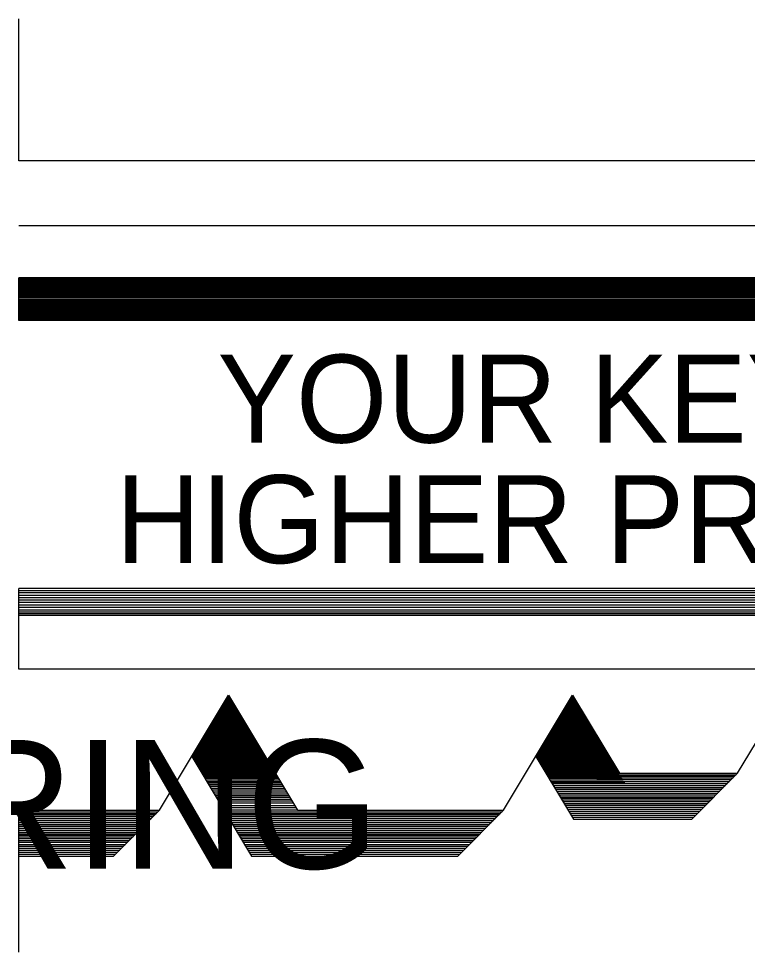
# Model space of a CAD drawing. Extents: x 22378.6 to 22422.6, y 22377.7 to 22411.7.
# Drawn here: x 22382.04 to 22382.601, y 22378.838 to 22379.557 of the extents above; entities that cross this region are included whole.
import ezdxf

# ---------------------------------------------------------------- set-up
doc = ezdxf.new("R2010")
doc.units = 0
for name, color, linetype in [('Level 1', 7, 'Continuous'), ('Level 10', 7, 'Continuous'), ('Level 2', 7, 'Continuous'), ('Level 7', 7, 'Continuous')]:
    doc.layers.add(name, color=color, linetype=linetype)

msp = doc.modelspace()

# ---------------------------------------------------------------- linework, layer by layer
at = {"layer": 'Level 1'}
msp.add_line((22382.04032, 22379.32481), (22382.04032, 22379.35744), dxfattribs=at)
at = {"layer": 'Level 10'}
msp.add_line((22383.12182, 22379.39769), (22382.04032, 22379.39769), dxfattribs=at)
at = {"layer": 'Level 2'}
for p, q in [((22383.17045, 22379.35744), (22382.04032, 22379.35744)), ((22383.17145, 22379.35669), (22382.04032, 22379.35669)), ((22383.17232, 22379.35594), (22382.04032, 22379.35594)), ((22383.17332, 22379.35506), (22382.04032, 22379.35506)), ((22383.17445, 22379.35419), (22382.04032, 22379.35419)), ((22383.17545, 22379.35331), (22382.04032, 22379.35331)), ((22383.1767, 22379.35231), (22382.04032, 22379.35231)), ((22383.1777, 22379.35144), (22382.04032, 22379.35144)), ((22383.17895, 22379.35044), (22382.04032, 22379.35044)), ((22383.1802, 22379.34944), (22382.04032, 22379.34944)), ((22383.1812, 22379.34856), (22382.04032, 22379.34856)), ((22383.18232, 22379.34756), (22382.04032, 22379.34756)), ((22383.1837, 22379.34656), (22382.04032, 22379.34656)), ((22383.1847, 22379.34569), (22382.04032, 22379.34569)), ((22383.1857, 22379.34481), (22382.04032, 22379.34481)), ((22383.18695, 22379.34381), (22382.04032, 22379.34381)), ((22383.1882, 22379.34281), (22382.04032, 22379.34281)), ((22383.18932, 22379.34181), (22382.04032, 22379.34181)), ((22383.1907, 22379.34069), (22382.04032, 22379.34069)), ((22383.19182, 22379.33981), (22382.04032, 22379.33981)), ((22383.19295, 22379.33881), (22382.04032, 22379.33881)), ((22383.19432, 22379.33769), (22382.04032, 22379.33769)), ((22383.19557, 22379.33669), (22382.04032, 22379.33669)), ((22383.19645, 22379.33594), (22382.04032, 22379.33594)), ((22383.1977, 22379.33494), (22382.04032, 22379.33494)), ((22383.19882, 22379.33394), (22382.04032, 22379.33394)), ((22383.19995, 22379.33306), (22382.04032, 22379.33306)), ((22383.20095, 22379.33219), (22382.04032, 22379.33219)), ((22383.20195, 22379.33144), (22382.04032, 22379.33144)), ((22383.20332, 22379.33031), (22382.04032, 22379.33031)), ((22383.2042, 22379.32956), (22382.04032, 22379.32956)), ((22383.2052, 22379.32869), (22382.04032, 22379.32869)), ((22383.20607, 22379.32794), (22382.04032, 22379.32794)), ((22383.20707, 22379.32719), (22382.04032, 22379.32719)), ((22383.20782, 22379.32656), (22382.04032, 22379.32656)), ((22383.2087, 22379.32581), (22382.04032, 22379.32581)), ((22383.20932, 22379.32531), (22382.04032, 22379.32531)), ((22383.20995, 22379.32481), (22382.04032, 22379.32481)), ((22383.26782, 22379.11831), (22382.04032, 22379.11831)), ((22382.04032, 22379.05631), (22382.04032, 22379.11831)), ((22383.26582, 22379.11669), (22382.04032, 22379.11669)), ((22383.2637, 22379.11494), (22382.04032, 22379.11494)), ((22383.26132, 22379.11294), (22382.04032, 22379.11294)), ((22383.25932, 22379.11131), (22382.04032, 22379.11131)), ((22383.25695, 22379.10931), (22382.04032, 22379.10931)), ((22383.25482, 22379.10756), (22382.04032, 22379.10756)), ((22383.25257, 22379.10569), (22382.04032, 22379.10569)), ((22383.25007, 22379.10369), (22382.04032, 22379.10369)), ((22383.24782, 22379.10181), (22382.04032, 22379.10181)), ((22383.2457, 22379.10006), (22382.04032, 22379.10006)), ((22383.2442, 22379.09881), (22382.04032, 22379.09881)), ((22383.24282, 22379.09769), (22382.04032, 22379.09769)), ((22383.19282, 22379.05631), (22382.04032, 22379.05631)), ((22382.19745, 22379.02906), (22382.2062, 22379.02906)), ((22382.19807, 22379.03006), (22382.20557, 22379.03006)), ((22382.1987, 22379.03106), (22382.20495, 22379.03106)), ((22382.19932, 22379.03206), (22382.20432, 22379.03206)), ((22382.19982, 22379.03306), (22382.20382, 22379.03306)), ((22382.20045, 22379.03406), (22382.2032, 22379.03406)), ((22382.20107, 22379.03506), (22382.20257, 22379.03506)), ((22382.4622, 22379.02906), (22382.47095, 22379.02906)), ((22382.46282, 22379.03006), (22382.47032, 22379.03006)), ((22382.46345, 22379.03106), (22382.4697, 22379.03106)), ((22382.46407, 22379.03206), (22382.46907, 22379.03206)), ((22382.46457, 22379.03306), (22382.46857, 22379.03306)), ((22382.46507, 22379.03381), (22382.46807, 22379.03381)), ((22382.46557, 22379.03456), (22382.46757, 22379.03456)), ((22382.46595, 22379.03531), (22382.4672, 22379.03531)), ((22382.19345, 22379.02206), (22382.21032, 22379.02206)), ((22382.19382, 22379.02306), (22382.2097, 22379.02306)), ((22382.19445, 22379.02406), (22382.2092, 22379.02406)), ((22382.19507, 22379.02506), (22382.20857, 22379.02506)), ((22382.1957, 22379.02606), (22382.20795, 22379.02606)), ((22382.19632, 22379.02706), (22382.20732, 22379.02706)), ((22382.19682, 22379.02806), (22382.2067, 22379.02806)), ((22382.4582, 22379.02206), (22382.47507, 22379.02206)), ((22382.45857, 22379.02306), (22382.47445, 22379.02306)), ((22382.4592, 22379.02406), (22382.47395, 22379.02406)), ((22382.45982, 22379.02506), (22382.47332, 22379.02506)), ((22382.46045, 22379.02606), (22382.4727, 22379.02606)), ((22382.46107, 22379.02706), (22382.47207, 22379.02706)), ((22382.46157, 22379.02806), (22382.47145, 22379.02806)), ((22382.18907, 22379.01506), (22382.21457, 22379.01506)), ((22382.1897, 22379.01606), (22382.21395, 22379.01606)), ((22382.19032, 22379.01706), (22382.21332, 22379.01706)), ((22382.19095, 22379.01806), (22382.2127, 22379.01806)), ((22382.19157, 22379.01906), (22382.2122, 22379.01906)), ((22382.1922, 22379.02006), (22382.21157, 22379.02006)), ((22382.19282, 22379.02106), (22382.21095, 22379.02106)), ((22382.45382, 22379.01506), (22382.47932, 22379.01506)), ((22382.45445, 22379.01606), (22382.4787, 22379.01606)), ((22382.45507, 22379.01706), (22382.47807, 22379.01706)), ((22382.4557, 22379.01806), (22382.47745, 22379.01806)), ((22382.45632, 22379.01906), (22382.47695, 22379.01906)), ((22382.45695, 22379.02006), (22382.47632, 22379.02006)), ((22382.45757, 22379.02106), (22382.4757, 22379.02106)), ((22382.18495, 22379.00806), (22382.2187, 22379.00806)), ((22382.18545, 22379.00906), (22382.21807, 22379.00906)), ((22382.18607, 22379.01006), (22382.21757, 22379.01006)), ((22382.1867, 22379.01106), (22382.21695, 22379.01106)), ((22382.18732, 22379.01206), (22382.21632, 22379.01206)), ((22382.18795, 22379.01306), (22382.2157, 22379.01306)), ((22382.18845, 22379.01406), (22382.21507, 22379.01406)), ((22382.4497, 22379.00806), (22382.48345, 22379.00806)), ((22382.4502, 22379.00906), (22382.48282, 22379.00906)), ((22382.45082, 22379.01006), (22382.48232, 22379.01006)), ((22382.45145, 22379.01106), (22382.4817, 22379.01106)), ((22382.45207, 22379.01206), (22382.48107, 22379.01206)), ((22382.4527, 22379.01306), (22382.48045, 22379.01306)), ((22382.4532, 22379.01406), (22382.47982, 22379.01406)), ((22382.1802, 22379.00006), (22382.22345, 22379.00006)), ((22382.18082, 22379.00106), (22382.22295, 22379.00106)), ((22382.18145, 22379.00206), (22382.22232, 22379.00206)), ((22382.18207, 22379.00306), (22382.2217, 22379.00306)), ((22382.1827, 22379.00406), (22382.22107, 22379.00406)), ((22382.18332, 22379.00506), (22382.22057, 22379.00506)), ((22382.1837, 22379.00606), (22382.21995, 22379.00606)), ((22382.18432, 22379.00706), (22382.21932, 22379.00706)), ((22382.44495, 22379.00006), (22382.4882, 22379.00006)), ((22382.44557, 22379.00106), (22382.4877, 22379.00106)), ((22382.4462, 22379.00206), (22382.48707, 22379.00206)), ((22382.44682, 22379.00306), (22382.48645, 22379.00306)), ((22382.44745, 22379.00406), (22382.48582, 22379.00406)), ((22382.44807, 22379.00506), (22382.48532, 22379.00506)), ((22382.44845, 22379.00606), (22382.4847, 22379.00606)), ((22382.44907, 22379.00706), (22382.48407, 22379.00706)), ((22382.17595, 22378.99306), (22382.2277, 22378.99306)), ((22382.17645, 22378.99406), (22382.22707, 22378.99406)), ((22382.17707, 22378.99506), (22382.22645, 22378.99506)), ((22382.1777, 22378.99606), (22382.22595, 22378.99606)), ((22382.17832, 22378.99706), (22382.22532, 22378.99706)), ((22382.17895, 22378.99806), (22382.2247, 22378.99806)), ((22382.17957, 22378.99906), (22382.22407, 22378.99906)), ((22382.4407, 22378.99306), (22382.49245, 22378.99306)), ((22382.4412, 22378.99406), (22382.49182, 22378.99406)), ((22382.44182, 22378.99506), (22382.4912, 22378.99506)), ((22382.44245, 22378.99606), (22382.4907, 22378.99606)), ((22382.44307, 22378.99706), (22382.49007, 22378.99706)), ((22382.4437, 22378.99806), (22382.48945, 22378.99806)), ((22382.44432, 22378.99906), (22382.48882, 22378.99906)), ((22382.17357, 22378.98906), (22382.21945, 22378.91231)), ((22382.17357, 22378.98906), (22382.23007, 22378.98906)), ((22382.17407, 22378.99006), (22382.22945, 22378.99006)), ((22382.1742, 22378.98806), (22382.2307, 22378.98806)), ((22382.1747, 22378.99106), (22382.22882, 22378.99106)), ((22382.17482, 22378.98706), (22382.23132, 22378.98706)), ((22382.17532, 22378.99206), (22382.22832, 22378.99206)), ((22382.17532, 22378.98606), (22382.23182, 22378.98606)), ((22382.43832, 22378.98906), (22382.46732, 22378.94081)), ((22382.43832, 22378.98906), (22382.49482, 22378.98906)), ((22382.43882, 22378.99006), (22382.4942, 22378.99006)), ((22382.43895, 22378.98806), (22382.49545, 22378.98806)), ((22382.43945, 22378.99106), (22382.49357, 22378.99106)), ((22382.43957, 22378.98706), (22382.49607, 22378.98706)), ((22382.44007, 22378.99206), (22382.49307, 22378.99206)), ((22382.44007, 22378.98606), (22382.49657, 22378.98606)), ((22382.17595, 22378.98506), (22382.23245, 22378.98506)), ((22382.17657, 22378.98406), (22382.23282, 22378.98406)), ((22382.1772, 22378.98306), (22382.23345, 22378.98306)), ((22382.1777, 22378.98206), (22382.23407, 22378.98206)), ((22382.17832, 22378.98106), (22382.2347, 22378.98106)), ((22382.17895, 22378.98006), (22382.23532, 22378.98006)), ((22382.17957, 22378.97906), (22382.23595, 22378.97906)), ((22382.4407, 22378.98506), (22382.4972, 22378.98506)), ((22382.44132, 22378.98406), (22382.49757, 22378.98406)), ((22382.44195, 22378.98306), (22382.4982, 22378.98306)), ((22382.44245, 22378.98206), (22382.49882, 22378.98206)), ((22382.44307, 22378.98106), (22382.49945, 22378.98106)), ((22382.4437, 22378.98006), (22382.50007, 22378.98006)), ((22382.44432, 22378.97906), (22382.5007, 22378.97906)), ((22382.1802, 22378.97806), (22382.23657, 22378.97806)), ((22382.1807, 22378.97706), (22382.2372, 22378.97706)), ((22382.18132, 22378.97606), (22382.23782, 22378.97606)), ((22382.18195, 22378.97506), (22382.23845, 22378.97506)), ((22382.18245, 22378.97431), (22382.23895, 22378.97431)), ((22382.18295, 22378.97331), (22382.23945, 22378.97331)), ((22382.18357, 22378.97231), (22382.24007, 22378.97231)), ((22382.44495, 22378.97806), (22382.50132, 22378.97806)), ((22382.44545, 22378.97706), (22382.50195, 22378.97706)), ((22382.44607, 22378.97606), (22382.50257, 22378.97606)), ((22382.4467, 22378.97506), (22382.5032, 22378.97506)), ((22382.4472, 22378.97431), (22382.5037, 22378.97431)), ((22382.4477, 22378.97331), (22382.5042, 22378.97331)), ((22382.44832, 22378.97231), (22382.50482, 22378.97231)), ((22382.48532, 22378.97494), (22382.59245, 22378.97494)), ((22382.48532, 22378.97381), (22382.59132, 22378.97381)), ((22382.48532, 22378.97269), (22382.5902, 22378.97269)), ((22382.48532, 22378.97131), (22382.58882, 22378.97131)), ((22382.55832, 22378.94081), (22382.5937, 22378.97619)), ((22382.1842, 22378.97119), (22382.24082, 22378.97119)), ((22382.18495, 22378.96994), (22382.24157, 22378.96994)), ((22382.1857, 22378.96881), (22382.2422, 22378.96881)), ((22382.18645, 22378.96744), (22382.24307, 22378.96744)), ((22382.1872, 22378.96619), (22382.2437, 22378.96619)), ((22382.1882, 22378.96469), (22382.2447, 22378.96469)), ((22382.44895, 22378.97119), (22382.50557, 22378.97119)), ((22382.4497, 22378.96994), (22382.50632, 22378.96994)), ((22382.45045, 22378.96881), (22382.50695, 22378.96881)), ((22382.45082, 22378.96831), (22382.58582, 22378.96831)), ((22382.4517, 22378.96681), (22382.58432, 22378.96681)), ((22382.45257, 22378.96531), (22382.58282, 22378.96531)), ((22382.48532, 22378.96994), (22382.58745, 22378.96994)), ((22382.18895, 22378.96331), (22382.24545, 22378.96331)), ((22382.18982, 22378.96181), (22382.24632, 22378.96181)), ((22382.1907, 22378.96031), (22382.24732, 22378.96031)), ((22382.19145, 22378.95906), (22382.24807, 22378.95906)), ((22382.1922, 22378.95781), (22382.24882, 22378.95781)), ((22382.45345, 22378.96394), (22382.58145, 22378.96394)), ((22382.45432, 22378.96244), (22382.57995, 22378.96244)), ((22382.4552, 22378.96094), (22382.57845, 22378.96094)), ((22382.45607, 22378.95944), (22382.57695, 22378.95944)), ((22382.45707, 22378.95794), (22382.57545, 22378.95794)), ((22382.45757, 22378.95694), (22382.57445, 22378.95694)), ((22382.1932, 22378.95631), (22382.2497, 22378.95631)), ((22382.19395, 22378.95494), (22382.25045, 22378.95494)), ((22382.19482, 22378.95344), (22382.25132, 22378.95344)), ((22382.19607, 22378.95144), (22382.25257, 22378.95144)), ((22382.19707, 22378.94981), (22382.25357, 22378.94981)), ((22382.45832, 22378.95581), (22382.57332, 22378.95581)), ((22382.4592, 22378.95431), (22382.57182, 22378.95431)), ((22382.46007, 22378.95281), (22382.57032, 22378.95281)), ((22382.46082, 22378.95156), (22382.56907, 22378.95156)), ((22382.46182, 22378.94994), (22382.56745, 22378.94994)), ((22382.04032, 22378.94644), (22382.14745, 22378.94644)), ((22382.04032, 22378.94531), (22382.14632, 22378.94531)), ((22382.04032, 22378.94419), (22382.1452, 22378.94419)), ((22382.04032, 22378.94281), (22382.14382, 22378.94281)), ((22382.11332, 22378.91231), (22382.1487, 22378.94769)), ((22382.19807, 22378.94806), (22382.25457, 22378.94806)), ((22382.19907, 22378.94644), (22382.41232, 22378.94644)), ((22382.1997, 22378.94531), (22382.4112, 22378.94531)), ((22382.20045, 22378.94419), (22382.41007, 22378.94419)), ((22382.2012, 22378.94281), (22382.4087, 22378.94281)), ((22382.3782, 22378.91231), (22382.41357, 22378.94769)), ((22382.4627, 22378.94844), (22382.56595, 22378.94844)), ((22382.4637, 22378.94694), (22382.56445, 22378.94694)), ((22382.46445, 22378.94556), (22382.56307, 22378.94556)), ((22382.46557, 22378.94381), (22382.56132, 22378.94381)), ((22382.04032, 22378.94144), (22382.14245, 22378.94144)), ((22382.04032, 22378.93981), (22382.14082, 22378.93981)), ((22382.04032, 22378.93831), (22382.13932, 22378.93831)), ((22382.04032, 22378.93681), (22382.13782, 22378.93681)), ((22382.04032, 22378.93544), (22382.13645, 22378.93544)), ((22382.20207, 22378.94144), (22382.40732, 22378.94144)), ((22382.20307, 22378.93981), (22382.4057, 22378.93981)), ((22382.20395, 22378.93831), (22382.4042, 22378.93831)), ((22382.20482, 22378.93681), (22382.4027, 22378.93681)), ((22382.20557, 22378.93544), (22382.40132, 22378.93544)), ((22382.46645, 22378.94231), (22382.55982, 22378.94231)), ((22382.46732, 22378.94081), (22382.55832, 22378.94081)), ((22382.04032, 22378.93394), (22382.13495, 22378.93394)), ((22382.04032, 22378.93244), (22382.13345, 22378.93244)), ((22382.04032, 22378.93094), (22382.13195, 22378.93094)), ((22382.04032, 22378.92944), (22382.13045, 22378.92944)), ((22382.04032, 22378.92844), (22382.12945, 22378.92844)), ((22382.20657, 22378.93394), (22382.39982, 22378.93394)), ((22382.20745, 22378.93244), (22382.39832, 22378.93244)), ((22382.20832, 22378.93094), (22382.39682, 22378.93094)), ((22382.2092, 22378.92944), (22382.39532, 22378.92944)), ((22382.20982, 22378.92844), (22382.39432, 22378.92844)), ((22382.04032, 22378.92731), (22382.12832, 22378.92731)), ((22382.04032, 22378.92581), (22382.12682, 22378.92581)), ((22382.04032, 22378.92431), (22382.12532, 22378.92431)), ((22382.04032, 22378.92306), (22382.12407, 22378.92306)), ((22382.04032, 22378.92144), (22382.12245, 22378.92144)), ((22382.21045, 22378.92731), (22382.3932, 22378.92731)), ((22382.21132, 22378.92581), (22382.3917, 22378.92581)), ((22382.21232, 22378.92431), (22382.3902, 22378.92431)), ((22382.21307, 22378.92306), (22382.38895, 22378.92306)), ((22382.21395, 22378.92144), (22382.38732, 22378.92144)), ((22382.04032, 22378.91994), (22382.12095, 22378.91994)), ((22382.04032, 22378.91844), (22382.11945, 22378.91844)), ((22382.04032, 22378.91706), (22382.11807, 22378.91706)), ((22382.04032, 22378.91531), (22382.11632, 22378.91531)), ((22382.04032, 22378.91381), (22382.11482, 22378.91381)), ((22382.21495, 22378.91994), (22382.38582, 22378.91994)), ((22382.21582, 22378.91844), (22382.38432, 22378.91844)), ((22382.21657, 22378.91706), (22382.38295, 22378.91706)), ((22382.2177, 22378.91531), (22382.3812, 22378.91531)), ((22382.21857, 22378.91381), (22382.3797, 22378.91381)), ((22382.04032, 22378.91231), (22382.11332, 22378.91231)), ((22382.21945, 22378.91231), (22382.3782, 22378.91231))]:
    msp.add_line(p, q, dxfattribs=at)
at = {"layer": 'Level 7'}
for p, q in [((22382.04032, 22379.44769), (22382.04032, 22379.55706)), ((22383.06132, 22379.44769), (22382.04032, 22379.44769)), ((22382.1487, 22378.94769), (22382.20182, 22379.03631)), ((22382.20182, 22379.03631), (22382.25482, 22378.94769)), ((22382.41357, 22378.94769), (22382.46657, 22379.03631)), ((22382.46657, 22379.03631), (22382.5027, 22378.97619)), ((22382.5937, 22378.97619), (22382.6297, 22379.03631)), ((22382.5027, 22378.97619), (22382.5937, 22378.97619)), ((22382.04032, 22378.83831), (22382.04032, 22378.94769)), ((22382.04032, 22378.94769), (22382.1487, 22378.94769)), ((22382.25482, 22378.94769), (22382.41357, 22378.94769))]:
    msp.add_line(p, q, dxfattribs=at)

# ---------------------------------------------------------------- texts
at = {"layer": 'Level 2'}
for s, height, p in [('YOUR KEY TO', 0.0676868, (22382.19332, 22379.23069)), ('HIGHER PROFITS', 0.0676868, (22382.11507, 22379.13794)), ('ENGINEERING', 0.0989925, (22381.39145, 22378.90281))]:
    msp.add_text(s, height=height, dxfattribs=at).set_placement(p)

doc.saveas('drawing.dxf')
